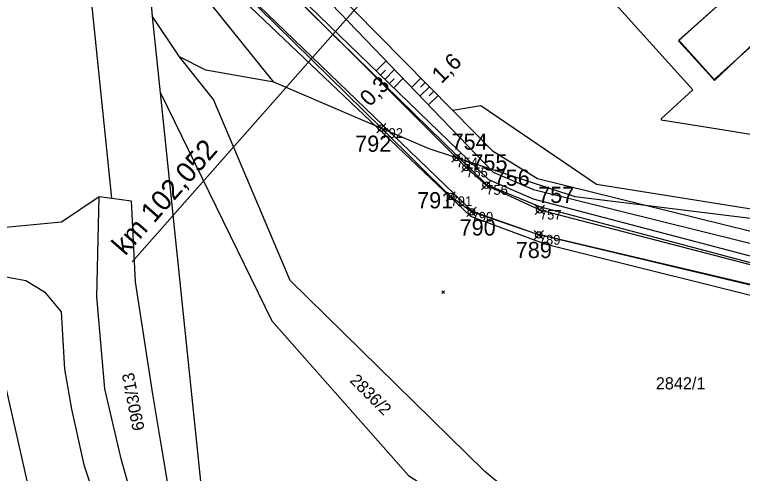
# Model space of a CAD drawing. Extents: x -800194 to -799078, y -1007177 to -1006597.
# Drawn here: x -799843.2 to -799753.2, y -1007080.7 to -1007023.9 of the extents above; entities that cross this region are included whole.
import ezdxf

# ---------------------------------------------------------------- set-up
doc = ezdxf.new("R2010")
doc.units = 0
for name, color, linetype in [('Obvod stavby', 7, 'Continuous'), ('Vrstva 13', 7, 'Continuous'), ('Vrstva 17', 7, 'Continuous'), ('Vrstva 23', 7, 'Continuous'), ('Vrstva 3', 7, 'Continuous'), ('Vrstva 48', 7, 'Continuous'), ('Vrstva 49', 7, 'Continuous'), ('Vrstva 51', 7, 'Continuous'), ('Vrstva 53', 7, 'Continuous'), ('Vrstva 55', 7, 'Continuous'), ('Vrstva 56', 7, 'Continuous'), ('Vrstva 57', 7, 'Continuous'), ('Vrstva 60', 7, 'Continuous')]:
    doc.layers.add(name, color=color, linetype=linetype)

msp = doc.modelspace()

# ---------------------------------------------------------------- linework, layer by layer
at = {"layer": 'Obvod stavby'}
for p, q in [((-799798.406, -1007038.516), (-799797.275, -1007037.385)), ((-799798.406, -1007037.385), (-799797.275, -1007038.516)), ((-799789.139, -1007042.162), (-799788.008, -1007041.03)), ((-799789.139, -1007041.03), (-799788.008, -1007042.162)), ((-799787.923, -1007043.378), (-799786.792, -1007042.247)), ((-799787.923, -1007042.247), (-799786.792, -1007043.378)), ((-799785.442, -1007045.558), (-799784.31, -1007044.427)), ((-799785.442, -1007044.427), (-799784.31, -1007045.558)), ((-799789.844, -1007046.952), (-799788.713, -1007045.82)), ((-799789.844, -1007045.82), (-799788.713, -1007046.952)), ((-799778.814, -1007048.62), (-799777.683, -1007047.489)), ((-799778.814, -1007047.489), (-799777.683, -1007048.62)), ((-799787.26, -1007048.871), (-799786.129, -1007047.739)), ((-799787.26, -1007047.739), (-799786.129, -1007048.871)), ((-799778.94, -1007051.723), (-799777.809, -1007050.591)), ((-799778.94, -1007050.591), (-799777.809, -1007051.723))]:
    msp.add_line(p, q, dxfattribs=at)
for points in [[(-799788.573, -1007041.596), (-799817.235, -1007012.921), (-799819.729, -1007011.289), (-799821.793, -1007008.319)], [(-799820.965, -1007015.295), (-799819.494, -1007016.617), (-799797.841, -1007037.951)], [(-799715.538, -1007076.136), (-799718.921, -1007072.582), (-799725.506, -1007066.383), (-799727.21, -1007065.372), (-799749.273, -1007058.083), (-799778.375, -1007051.157), (-799786.694, -1007048.305), (-799789.278, -1007046.386), (-799797.841, -1007037.951)], [(-799788.573, -1007041.596), (-799787.358, -1007042.812), (-799784.876, -1007044.993), (-799778.248, -1007048.055), (-799745.437, -1007056.58), (-799726.417, -1007061.681), (-799724.384, -1007062.827), (-799716.636, -1007069.686), (-799714.141, -1007072.185)]]:
    msp.add_lwpolyline(points, dxfattribs=at)
for centre in [(-799797.841, -1007037.951), (-799788.573, -1007041.596), (-799787.358, -1007042.812), (-799784.876, -1007044.993), (-799789.278, -1007046.386), (-799786.694, -1007048.305), (-799778.248, -1007048.055), (-799778.375, -1007051.157)]:
    msp.add_circle(centre, 0.4, dxfattribs=at)
at = {"layer": 'Vrstva 13'}
msp.add_lwpolyline([(-799805.067, -1007021.457), (-799784.005, -1007043.381), (-799779.029, -1007045.556), (-799742.637, -1007054.554), (-799725.892, -1007059.592)], dxfattribs=at)
at = {"layer": 'Vrstva 17'}
for points in [[(-799828.95, -1007006.881), (-799820.579, -1007016.712), (-799786.808, -1007048.821), (-799777.641, -1007052.247), (-799745.452, -1007060.292), (-799727.709, -1007066.187)], [(-799744.108, -1007040.301), (-799744.795, -1007042.69), (-799746.422, -1007047.465), (-799747.487, -1007048.694), (-799771.226, -1007044.934), (-799785.53, -1007035.198), (-799789.014, -1007035.746), (-799804.246, -1007020.27), (-799801.55, -1007019.072), (-799803.933, -1007010.185)]]:
    msp.add_lwpolyline(points, dxfattribs=at)
at = {"layer": 'Vrstva 23'}
msp.add_lwpolyline([(-799756.701, -1007031.945), (-799748.818, -1007024.882), (-799742.835, -1007031.56), (-799739.203, -1007028.306), (-799738.261, -1007029.357), (-799736.112, -1007027.467), (-799737.076, -1007026.37), (-799736.711, -1007026.049), (-799742.825, -1007019.446), (-799742.529, -1007019.177), (-799746.942, -1007014.309), (-799747.197, -1007014.54), (-799753.188, -1007007.931), (-799753.56, -1007008.268), (-799754.56, -1007007.163), (-799756.669, -1007009.071), (-799755.683, -1007010.172), (-799759.339, -1007013.448), (-799754.227, -1007019.154), (-799755.62, -1007020.402), (-799754.738, -1007021.386), (-799761.075, -1007027.063), (-799756.701, -1007031.945)], dxfattribs=at)
at = {"layer": 'Vrstva 3'}
msp.add_line((-799769.882, -1006987.807), (-799828.64, -1007054.5), dxfattribs=at)
at = {"layer": 'Vrstva 48'}
for p, q in [((-799798.468, -1007030.877), (-799797.238, -1007029.606)), ((-799797.93, -1007031.399), (-799797.324, -1007030.773)), ((-799797.391, -1007031.92), (-799796.198, -1007030.689)), ((-799796.852, -1007032.442), (-799796.265, -1007031.836)), ((-799796.313, -1007032.964), (-799795.158, -1007031.771)), ((-799792.942, -1007031.756), (-799794.089, -1007032.885)), ((-799792.415, -1007032.29), (-799792.992, -1007032.858)), ((-799791.889, -1007032.825), (-799793.049, -1007033.966)), ((-799790.837, -1007033.894), (-799792.01, -1007035.048)), ((-799791.363, -1007033.359), (-799791.947, -1007033.933))]:
    msp.add_line(p, q, dxfattribs=at)
at = {"layer": 'Vrstva 49'}
for p, q in [((-799790.372, -1007058.057), (-799790.018, -1007058.411)), ((-799790.372, -1007058.411), (-799790.018, -1007058.057))]:
    msp.add_line(p, q, dxfattribs=at)
for points in [[(-799823.433, -1006985.376), (-799817.838, -1006990.049), (-799815.5, -1006993.967), (-799810.13, -1006998.908), (-799803.933, -1007010.185), (-799801.55, -1007019.072), (-799804.246, -1007020.27), (-799789.014, -1007035.746), (-799784.101, -1007040.767), (-799778.537, -1007044.165), (-799742.314, -1007053.114), (-799725.901, -1007057.997)], [(-799823.433, -1006985.376), (-799822.824, -1006995.382), (-799809.853, -1007012.441), (-799805.067, -1007021.457), (-799784.005, -1007043.381), (-799779.029, -1007045.556), (-799742.637, -1007054.554), (-799725.892, -1007059.592)], [(-799822.824, -1006995.382), (-799817.689, -1007012.452), (-799816.629, -1007013.288), (-799784.593, -1007044.315), (-799779.066, -1007046.684), (-799743.002, -1007056.174), (-799726.202, -1007060.605)]]:
    msp.add_lwpolyline(points, dxfattribs=at)
at = {"layer": 'Vrstva 51'}
for points in [[(-799817.051, -1006918.973), (-799812.091, -1006931.542), (-799815.665, -1006943.128), (-799826.019, -1006959.481), (-799831.215, -1006965.513), (-799832.478, -1006972.309), (-799831.126, -1006986.858), (-799828.082, -1006983.271), (-799821.896, -1006976.034), (-799813.152, -1006974.923), (-799805.94, -1006982.791), (-799808.362, -1006984.771), (-799815.088, -1006977.554), (-799820.319, -1006978.428), (-799823.433, -1006985.376), (-799830.084, -1006997.726), (-799819.519, -1007011.695), (-799817.354, -1007013.08), (-799784.788, -1007044.956), (-799778.171, -1007047.694), (-799743.858, -1007056.783), (-799726.629, -1007061.89)], [(-799842.202, -1006982.511), (-799833.072, -1007000.361), (-799821.843, -1007014.249), (-799786.621, -1007048.212), (-799778.768, -1007050.961), (-799745.381, -1007058.848), (-799727.01, -1007064.42)]]:
    msp.add_lwpolyline(points, dxfattribs=at)
at = {"layer": 'Vrstva 53'}
msp.add_lwpolyline([(-799673.33, -1007118.14), (-799714.71, -1007110.97), (-799718.21, -1007083.69), (-799729.93, -1007087.54), (-799766.47, -1007095.84), (-799767.73, -1007094.8), (-799769.22, -1007093.56), (-799785.06, -1007080.42), (-799809.11, -1007056.81), (-799818.59, -1007034.4), (-799822.79, -1007029.13), (-799826.14, -1007024.13), (-799830.75, -1006966.73), (-799839.73, -1006961.33), (-799877.87, -1006942.17), (-799936.47, -1006903.99), (-799954.76, -1006895.45), (-799964.79, -1006890.84)], dxfattribs=at)
at = {"layer": 'Vrstva 55'}
for p, q in [((-799826.14, -1007024.13), (-799830.75, -1006966.73)), ((-799825.16, -1007033.58), (-799826.14, -1007024.13)), ((-799822.79, -1007029.13), (-799826.14, -1007024.13)), ((-799818.85, -1007094.38), (-799825.16, -1007033.58)), ((-799832.71, -1007046.42), (-799831.14, -1007046.62))]:
    msp.add_line(p, q, dxfattribs=at)
for points in [[(-799811.13, -1007032.26), (-799820.31, -1007020.81), (-799827.08, -1006963.79), (-799830.75, -1006966.73)], [(-799831.14, -1007046.62), (-799837.54, -1006984.31), (-799843.2, -1006977.69), (-799849.98, -1006977.29), (-799866.6, -1006981.12)], [(-799753.19, -1007008), (-799759.37, -1007013.49), (-799769.21, -1007022.23), (-799759.34, -1007033.19), (-799763.24, -1007036.79), (-799763.26, -1007036.9), (-799756.25, -1007038.04), (-799746.93, -1007039.54), (-799742.61, -1007039.98), (-799738.64, -1007038.58), (-799744.1, -1007032.52), (-799742.99, -1007031.53), (-799739, -1007034.9), (-799733.28, -1007029.82), (-799736.83, -1007026.06), (-799742.84, -1007019.43), (-799742.54, -1007019.16), (-799746.93, -1007014.32), (-799747.23, -1007014.58), (-799749.47, -1007012.1), (-799753.19, -1007008)], [(-799769.22, -1007093.56), (-799785.06, -1007080.42), (-799809.11, -1007056.81), (-799818.59, -1007034.4), (-799822.79, -1007029.13)], [(-799811.13, -1007032.26), (-799819.54, -1007030.79), (-799822.79, -1007029.13)], [(-799727.16, -1007050.52), (-799734.57, -1007049.13), (-799749.18, -1007049.49), (-799773.9, -1007046.46), (-799791.91, -1007040.49), (-799811.13, -1007032.26)], [(-799825.16, -1007033.58), (-799811.39, -1007061.77), (-799794.49, -1007080.93), (-799774.66, -1007093.65)], [(-799846.07, -1007050.35), (-799837.39, -1007049.52), (-799832.71, -1007046.42)], [(-799823.03, -1007089.38), (-799825.77, -1007089.63), (-799827.26, -1007088.72), (-799830.02, -1007078.85), (-799832.03, -1007070.18), (-799833.02, -1007058.82), (-799832.71, -1007046.42)], [(-799831.14, -1007046.62), (-799828.75, -1007046.93), (-799828.27, -1007056.97), (-799826.13, -1007070.87), (-799825.16, -1007076.77), (-799823.03, -1007089.38)], [(-799858.84, -1007065.67), (-799858.76, -1007060.77), (-799858.72, -1007059.86), (-799857.59, -1007058.97), (-799845.38, -1007056.13), (-799841.77, -1007056.79), (-799839.5, -1007058.21), (-799837.43, -1007060.68), (-799836.99, -1007067.77), (-799836.14, -1007072.71), (-799834.61, -1007079.6), (-799832.83, -1007084.94), (-799830.58, -1007092.52), (-799828.9, -1007096.44), (-799827.32, -1007101.2), (-799825.89, -1007106.02), (-799824.52, -1007111.92), (-799824.25, -1007121.19), (-799824.17, -1007122.98), (-799825.87, -1007124.09), (-799830.82, -1007128.75)], [(-799846.34, -1007114.47), (-799834.79, -1007111.87), (-799845.89, -1007062.76), (-799858.84, -1007065.67)]]:
    msp.add_lwpolyline(points, dxfattribs=at)
at = {"layer": 'Vrstva 56'}
for p, q in [((-799761.09, -1007027.15), (-799755.06, -1007021.69)), ((-799757.32, -1007031.32), (-799761.09, -1007027.15)), ((-799756.64, -1007032.07), (-799751.58, -1007027.23)), ((-799756.64, -1007032.07), (-799757.32, -1007031.32))]:
    msp.add_line(p, q, dxfattribs=at)
at = {"layer": 'Vrstva 60'}
for p, q in [((-799797.841, -1007037.951), (-799797.841, -1007037.951)), ((-799788.573, -1007041.596), (-799788.573, -1007041.596)), ((-799787.358, -1007042.812), (-799787.358, -1007042.812)), ((-799784.876, -1007044.993), (-799784.876, -1007044.993)), ((-799789.279, -1007046.386), (-799789.279, -1007046.386)), ((-799786.694, -1007048.305), (-799786.694, -1007048.305)), ((-799778.248, -1007048.055), (-799778.248, -1007048.055)), ((-799778.375, -1007051.157), (-799778.375, -1007051.157))]:
    msp.add_line(p, q, dxfattribs=at)

# ---------------------------------------------------------------- texts
at = {"layer": 'Obvod stavby'}
for s, p in [('792', (-799801.078, -1007040.869)), ('754', (-799789.162, -1007040.614)), ('755', (-799786.711, -1007043.184)), ('756', (-799783.955, -1007045.067)), ('757', (-799778.457, -1007047.202)), ('791', (-799793.418, -1007047.864)), ('790', (-799788.168, -1007051.23)), ('789', (-799781.228, -1007054.017))]:
    msp.add_text(s, height=2, rotation=360, dxfattribs=at).set_placement(p)
at = {"layer": 'Vrstva 3'}
msp.add_text('km 102,052', height=2.5, rotation=48.61928, dxfattribs=at).set_placement((-799829.503, -1007053.837))
at = {"layer": 'Vrstva 48'}
for s, rotation, p in [('1,6', 44.54475, (-799790.416, -1007032.518)), ('0,3', 45.91665, (-799799.272, -1007035.389))]:
    msp.add_text(s, height=2, rotation=rotation, dxfattribs=at).set_placement(p)
at = {"layer": 'Vrstva 57'}
for s, rotation, p in [('6903/13', 101, (-799827.085, -1007075.212)), ('2836/2', 315, (-799801.844, -1007069.261))]:
    msp.add_text(s, height=1.5, rotation=rotation, dxfattribs=at).set_placement(p)
msp.add_text('2842/1', height=1.5, dxfattribs=at).set_placement((-799763.91, -1007070.26))
at = {"layer": 'Vrstva 60'}
for s, p in [('792', (-799797.841, -1007039.151)), ('754', (-799788.573, -1007042.796)), ('755', (-799787.358, -1007044.012)), ('756', (-799784.876, -1007046.193)), ('791', (-799789.279, -1007047.586)), ('790', (-799786.694, -1007049.505)), ('757', (-799778.248, -1007049.255)), ('789', (-799778.375, -1007052.357))]:
    msp.add_text(s, height=1.2, dxfattribs=at).set_placement(p)

doc.saveas('drawing.dxf')
